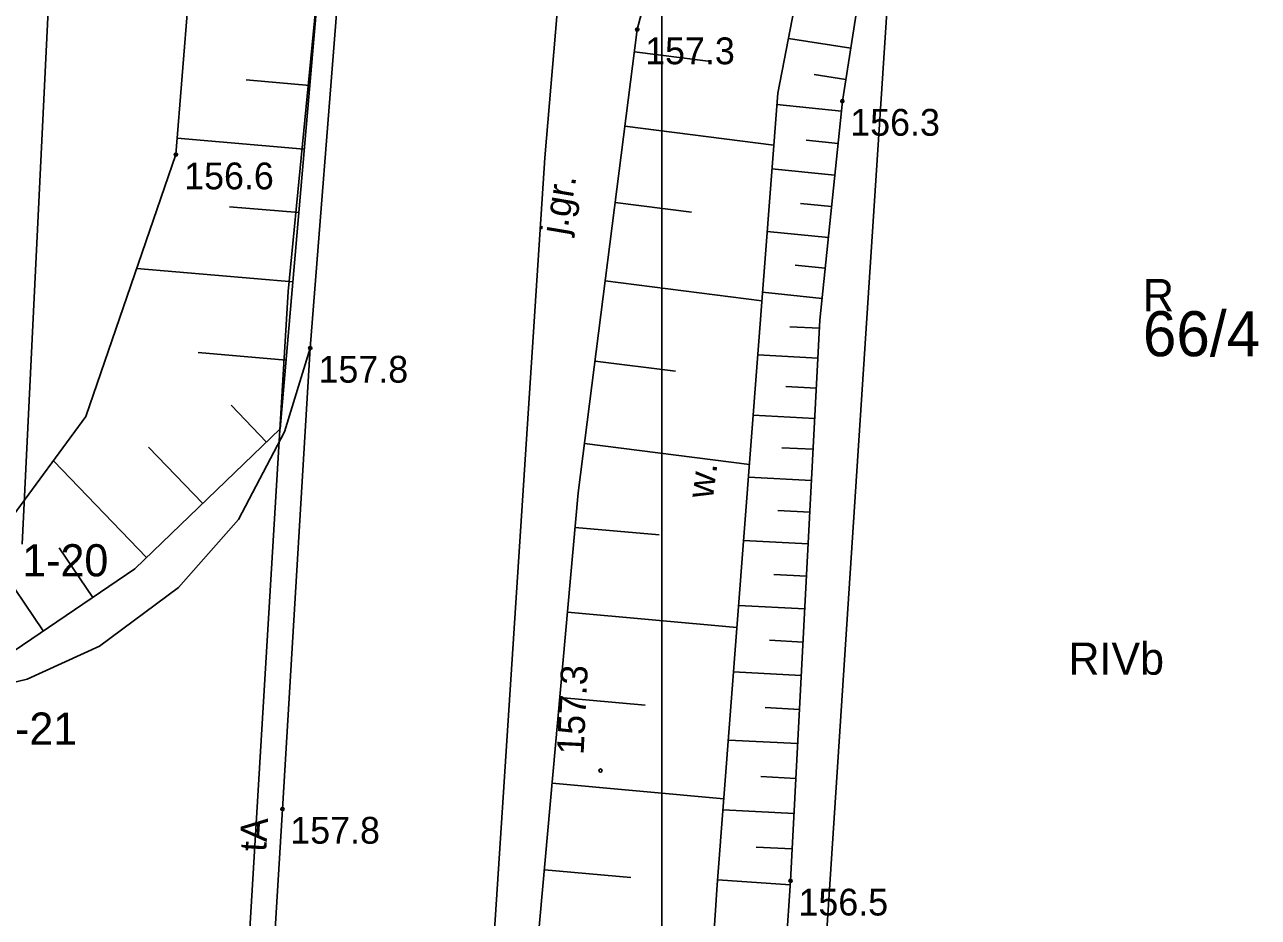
# Model space of a CAD drawing. Extents: x 5598798 to 5599616, y 5661498 to 5662453.
# Drawn here: x 5599182.17 to 5599216.69, y 5661914.76 to 5661939.74 of the extents above; entities that cross this region are included whole.
import ezdxf

# ---------------------------------------------------------------- set-up
doc = ezdxf.new("R2010")
doc.units = 0
for name, color, linetype in [('BUBZ_L_1', 7, 'Continuous'), ('Dzialki', 7, 'Continuous'), ('Kontury', 7, 'Continuous'), ('KTJZ_E_T_0', 7, 'Continuous'), ('KTJZ_L_0', 7, 'Continuous'), ('KTKR_L_0', 7, 'Continuous'), ('Numery_dzialek', 7, 'Continuous'), ('Numery_konturow', 7, 'Continuous'), ('Numery_punktow', 7, 'Continuous'), ('Numery_uzytkow', 7, 'Continuous'), ('Podzial_sekcyjny_podstawowy', 7, 'Continuous'), ('PTRW_E_T_1', 7, 'Continuous'), ('PTRW_L_0', 7, 'Continuous'), ('RTPW_T_0', 7, 'Continuous'), ('SUPT_E_T_0', 7, 'Continuous'), ('SUPT_L_0', 7, 'Continuous'), ('Uzytki', 7, 'Continuous')]:
    doc.layers.add(name, color=color, linetype=linetype)

# ---------------------------------------------------------------- blocks, each defined once
blk = doc.blocks.new('2_RTPW01')
blk.add_circle((0, 0), 0.045)

msp = doc.modelspace()

# ---------------------------------------------------------------- linework, layer by layer
at = {"layer": 'BUBZ_L_1'}
for p, q in [((5599186.4, 5661936.1), (5599188.51, 5661962.71)), ((5599192.22, 5661961.41), (5599190.05, 5661936.96)), ((5599205.42, 5661948.94), (5599203.24, 5661937.82)), ((5599199.31, 5661939.6), (5599201.49, 5661948.04)), ((5599205.05, 5661937.6), (5599206.04, 5661943.86)), ((5599197.66, 5661926.64), (5599199.31, 5661939.6)), ((5599205.28379, 5661939.078309), (5599203.540724, 5661939.353969)), ((5599199.231067, 5661938.980021), (5599201.29766, 5661938.716913)), ((5599205.14596, 5661938.206776), (5599204.25841, 5661938.347139)), ((5599190.145673, 5661938.037973), (5599188.362222, 5661938.196259)), ((5599203.24, 5661937.82), (5599201.55, 5661915.67)), ((5599204.42, 5661931.47), (5599205.05, 5661937.6)), ((5599205.020938, 5661937.317226), (5599203.215794, 5661937.502746)), ((5599190.05, 5661936.96), (5599189.32, 5661928.43)), ((5599198.966049, 5661936.898423), (5599203.129245, 5661936.368386)), ((5599189.989608, 5661936.254329), (5599186.43635, 5661936.558418)), ((5599204.928178, 5661936.414654), (5599204.037461, 5661936.506195)), ((5599183.88, 5661928.77), (5599186.4, 5661936.1)), ((5599204.836636, 5661935.523936), (5599203.0786, 5661935.704615)), ((5599198.694162, 5661934.762875), (5599200.82971, 5661934.490988)), ((5599189.837564, 5661934.477699), (5599187.897009, 5661934.643773)), ((5599204.746297, 5661934.644919), (5599203.878824, 5661934.734072)), ((5599204.657144, 5661933.777446), (5599202.944987, 5661933.95341)), ((5599189.671491, 5661932.537145), (5599185.303627, 5661932.910948)), ((5599204.569162, 5661932.921368), (5599203.724328, 5661933.008194)), ((5599198.415229, 5661932.571978), (5599202.797022, 5661932.014111)), ((5599204.482335, 5661932.076534), (5599202.814861, 5661932.247906)), ((5599203.6, 5661915.78), (5599204.42, 5661931.47)), ((5599204.408079, 5661931.241911), (5599203.576409, 5661931.285376)), ((5599189.484589, 5661930.353213), (5599187.026757, 5661930.563555)), ((5599198.129066, 5661930.324298), (5599200.376746, 5661930.038135)), ((5599204.364614, 5661930.41024), (5599202.681362, 5661930.498211)), ((5599204.320629, 5661929.568614), (5599203.468929, 5661929.613126)), ((5599188.933531, 5661928.057774), (5599187.94282, 5661929.086394)), ((5599181.74, 5661925.86), (5599183.88, 5661928.77)), ((5599204.276117, 5661928.716914), (5599202.552327, 5661928.807004)), ((5599189.32, 5661928.43), (5599185.25, 5661924.51)), ((5599187.150471, 5661926.340429), (5599185.637613, 5661927.911178)), ((5599197.835486, 5661928.018363), (5599202.447356, 5661927.431203)), ((5599204.231072, 5661927.855019), (5599203.35886, 5661927.900603)), ((5599185.579723, 5661924.827571), (5599182.971912, 5661927.535171)), ((5599204.185488, 5661926.982807), (5599202.420183, 5661927.075067)), ((5599195.64, 5661904.18), (5599197.66, 5661926.64)), ((5599204.139358, 5661926.100155), (5599203.246141, 5661926.146837)), ((5599197.572756, 5661925.669946), (5599199.926713, 5661925.458237)), ((5599182.688462, 5661922.77452), (5599180.928847, 5661925.371681)), ((5599184.072896, 5661923.712495), (5599183.134922, 5661925.096929)), ((5599204.092676, 5661925.206938), (5599202.284858, 5661925.301419)), ((5599185.25, 5661924.51), (5599181.87, 5661922.22)), ((5599204.045436, 5661924.303029), (5599203.130707, 5661924.350835)), ((5599203.997629, 5661923.3883), (5599202.146273, 5661923.485056)), ((5599197.359602, 5661923.299936), (5599202.099622, 5661922.87363)), ((5599203.949251, 5661922.462621), (5599203.012493, 5661922.511579)), ((5599203.900294, 5661921.525863), (5599202.004351, 5661921.62495)), ((5599197.144996, 5661920.913764), (5599199.531168, 5661920.699157)), ((5599203.85075, 5661920.577891), (5599202.891431, 5661920.628028)), ((5599203.800614, 5661919.618573), (5599201.85901, 5661919.720046)), ((5599203.749877, 5661918.647771), (5599202.767455, 5661918.699115)), ((5599196.928925, 5661918.511319), (5599201.733815, 5661918.079178)), ((5599203.698533, 5661917.665349), (5599201.71017, 5661917.769266)), ((5599203.646575, 5661916.671167), (5599202.640493, 5661916.723747)), ((5599196.711377, 5661916.092436), (5599199.130259, 5661915.874888)), ((5599203.592133, 5661915.665197), (5599201.560257, 5661915.804429)), ((5599202.37, 5661897.83), (5599203.6, 5661915.78)), ((5599201.55, 5661915.67), (5599200.33, 5661897.67))]:
    msp.add_line(p, q, dxfattribs=at)
at = {"layer": 'Dzialki'}
for p, q in [((5599182.1, 5661925.2), (5599183.8, 5661960.37)), ((5599207.13, 5661952.92), (5599202.8, 5661886.51))]:
    msp.add_line(p, q, dxfattribs=at)
at = {"layer": 'Kontury'}
for p, q in [((5599182.1, 5661925.2), (5599183.8, 5661960.37)), ((5599207.13, 5661952.92), (5599202.8, 5661886.51))]:
    msp.add_line(p, q, dxfattribs=at)
at = {"layer": 'KTJZ_L_0'}
for p, q in [((5599199.1, 5661963.93), (5599196.72, 5661936.01)), ((5599191.7, 5661950.38), (5599190.16, 5661930.69)), ((5599199.31, 5661939.6), (5599201.49, 5661948.04)), ((5599197.66, 5661926.64), (5599199.31, 5661939.6)), ((5599196.72, 5661936.01), (5599194.99, 5661909.33)), ((5599189.38, 5661917.79), (5599190.16, 5661930.69)), ((5599190.16, 5661930.69), (5599189.44, 5661928.34)), ((5599188.15, 5661925.89), (5599189.44, 5661928.34)), ((5599195.64, 5661904.18), (5599197.66, 5661926.64)), ((5599186.47, 5661923.99), (5599188.15, 5661925.89)), ((5599184.26, 5661922.35), (5599186.47, 5661923.99)), ((5599182.24, 5661921.42), (5599184.26, 5661922.35)), ((5599180.16, 5661920.93), (5599182.24, 5661921.42)), ((5599188.72, 5661906.93), (5599189.38, 5661917.79))]:
    msp.add_line(p, q, dxfattribs=at)
at = {"layer": 'KTKR_L_0'}
for p, q in [((5599189.44, 5661928.34), (5599190.16, 5661930.69)), ((5599188.15, 5661925.89), (5599189.44, 5661928.34)), ((5599186.47, 5661923.99), (5599188.15, 5661925.89)), ((5599184.26, 5661922.35), (5599186.47, 5661923.99)), ((5599182.24, 5661921.42), (5599184.26, 5661922.35)), ((5599180.16, 5661920.93), (5599182.24, 5661921.42))]:
    msp.add_line(p, q, dxfattribs=at)
at = {"layer": 'Podzial_sekcyjny_podstawowy'}
msp.add_line((5599200, 5661750), (5599200, 5662000), dxfattribs=at)
at = {"layer": 'PTRW_L_0'}
for p, q in [((5599201.49, 5661948.04), (5599199.31, 5661939.6)), ((5599205.05, 5661937.6), (5599206.04, 5661943.86)), ((5599199.31, 5661939.6), (5599197.66, 5661926.64)), ((5599204.42, 5661931.47), (5599205.05, 5661937.6)), ((5599203.6, 5661915.78), (5599204.42, 5661931.47)), ((5599197.66, 5661926.64), (5599195.64, 5661904.18)), ((5599202.37, 5661897.83), (5599203.6, 5661915.78))]:
    msp.add_line(p, q, dxfattribs=at)
at = {"layer": 'SUPT_L_0'}
for p, q in [((5599193.309647, 5661971.20769), (5599189.54249, 5661932.273767)), ((5599189.54249, 5661932.273767), (5599187.842687, 5661904.061861))]:
    msp.add_line(p, q, dxfattribs=at)
at = {"layer": 'Uzytki'}
for p, q in [((5599182.1, 5661925.2), (5599183.8, 5661960.37)), ((5599207.13, 5661952.92), (5599202.8, 5661886.51))]:
    msp.add_line(p, q, dxfattribs=at)

# ---------------------------------------------------------------- block references
at = {"layer": 'RTPW_T_0', "rotation": -3.0000000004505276e-06}
for p in [(5599199.31, 5661939.6), (5599205.05, 5661937.6), (5599186.4, 5661936.1), (5599190.16, 5661930.69), (5599189.38, 5661917.79), (5599203.6, 5661915.78)]:
    msp.add_blockref('2_RTPW01', p, dxfattribs=at)
at = {"layer": 'RTPW_T_0'}
msp.add_blockref('2_RTPW01', (5599198.281212, 5661918.865976), dxfattribs=at)

# ---------------------------------------------------------------- texts
at = {"layer": 'KTJZ_E_T_0'}
msp.add_text('j.gr.', height=0.75, rotation=80.400005, dxfattribs=at).set_placement((5599197.332352, 5661933.828045))
at = {"layer": 'Numery_dzialek'}
msp.add_text('66/4', height=1.26, dxfattribs=at).set_placement((5599213.45913, 5661930.460492))
at = {"layer": 'Numery_konturow'}
msp.add_text('RIVb', height=0.9, dxfattribs=at).set_placement((5599211.3748, 5661921.548104))
at = {"layer": 'Numery_punktow'}
for s, p in [('1-20', (5599182.1, 5661924.3)), ('1-21', (5599181.23, 5661919.59))]:
    msp.add_text(s, height=0.9, dxfattribs=at).set_placement(p)
at = {"layer": 'Numery_uzytkow'}
msp.add_text('R', height=0.9, dxfattribs=at).set_placement((5599213.45913, 5661931.720492))
at = {"layer": 'PTRW_E_T_1'}
msp.add_text('w.', height=0.75, rotation=82.499987, dxfattribs=at).set_placement((5599201.424411, 5661926.450947))
at = {"layer": 'RTPW_T_0'}
for s, p in [('157.3', (5599199.53, 5661938.63)), ('156.3', (5599205.27, 5661936.63)), ('156.6', (5599186.63, 5661935.13)), ('157.8', (5599190.39, 5661929.72)), ('157.8', (5599189.6, 5661916.82)), ('156.5', (5599203.82, 5661914.81))]:
    msp.add_text(s, height=0.75, dxfattribs=at).set_placement(p)
msp.add_text('157.3', height=0.75, rotation=87.224183, dxfattribs=at).set_placement((5599197.806583, 5661919.294685))
at = {"layer": 'SUPT_E_T_0'}
msp.add_text('tA', height=0.75, rotation=86.552038, dxfattribs=at).set_placement((5599188.924779, 5661916.583452))

doc.saveas('drawing.dxf')
